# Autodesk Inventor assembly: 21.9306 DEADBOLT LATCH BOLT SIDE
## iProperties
Created: 2012-07
Part Number: 21.9306 DEADBOLT LATCH BOLT SIDE
Document SubType Name: Assembly
Designer: Administrator
Mass: 85.7794 g
Surface Area: 100.728 cm^2
Volume: 13.2573 cm^3
Density: 6.47038 g/cm^3
Author: Administrator
